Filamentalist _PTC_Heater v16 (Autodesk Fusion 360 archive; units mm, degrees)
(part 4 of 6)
sketch "Sketch176" plane through (0, 74.3239, 0) normal (0, -1, 0) x axis (1, 0, 0)
  line L1 (102.2613, 77.8502) -> (-16.9087, 77.8502)
  line L2 (103.5313, 74.9038) -> (103.5313, 76.5802)
  line L3 (109.0177, 71.0938) -> (107.3413, 71.0938)
  line L4 (110.2877, -10.1662) -> (110.2877, 69.8238)
  line L5 (107.3413, -11.4362) -> (109.0177, -11.4362)
  line L6 (109.0177, -19.0562) -> (107.3413, -19.0562)
  line L7 (110.2877, -71.6662) -> (110.2877, -20.3262)
  line L8 (107.3413, -72.9362) -> (109.0177, -72.9362)
  line L9 (109.0177, -80.5562) -> (107.3413, -80.5562)
  line L10 (110.2877, -133.1662) -> (110.2877, -81.8262)
  line L11 (107.3413, -134.4362) -> (109.0177, -134.4362)
  line L12 (109.0177, -142.0562) -> (107.3413, -142.0562)
  line L13 (110.2877, -222.8162) -> (110.2877, -143.3262)
  line L14 (107.3413, -224.0862) -> (109.0177, -224.0862)
  line L15 (103.5313, -229.5726) -> (103.5313, -227.8962)
  line L16 (-16.9087, -230.8426) -> (102.2613, -230.8426)
  line L17 (-18.1787, -227.8962) -> (-18.1787, -229.5726)
  line L18 (-23.6651, -224.0862) -> (-21.9887, -224.0862)
  line L19 (-24.9351, -143.3262) -> (-24.9351, -222.8162)
  line L20 (-21.9887, -142.0562) -> (-23.6651, -142.0562)
  line L21 (-23.6651, -134.4362) -> (-21.9887, -134.4362)
  line L22 (-24.9351, -81.8262) -> (-24.9351, -133.1662)
  line L23 (-21.9887, -80.5562) -> (-23.6651, -80.5562)
  line L24 (-23.6651, -72.9362) -> (-21.9887, -72.9362)
  line L25 (-24.9351, -20.3262) -> (-24.9351, -71.6662)
  line L26 (-21.9887, -19.0562) -> (-23.6651, -19.0562)
  line L27 (-23.6651, -11.4362) -> (-21.9887, -11.4362)
  line L28 (-24.9351, 22.1988) -> (-24.9351, -10.1662)
  line L29 (-23.2587, 22.1988) -> (-24.9351, 22.1988)
  line L30 (-23.2587, 55.8538) -> (-23.2587, 22.1988)
  line L31 (-24.9351, 55.8538) -> (-23.2587, 55.8538)
  line L32 (-24.9351, 69.8238) -> (-24.9351, 55.8538)
  line L33 (-21.9887, 71.0938) -> (-23.6651, 71.0938)
  line L34 (-18.1787, 76.5802) -> (-18.1787, 74.9038)
  line L35 (-20.8387, 78.9678) -> (106.1913, 78.9678)
  line L36 (-26.0527, -226.7462) -> (-26.0527, 73.7538)
  line L37 (106.1913, -231.9602) -> (-20.8387, -231.9602)
  line L38 (111.4053, 73.7538) -> (111.4053, -226.7462)
  circle C1 centre (-21.9887, -15.2462) radius 1.27
  circle C2 centre (107.3413, -15.2462) radius 1.27
  circle C3 centre (107.3413, -76.7462) radius 1.27
  circle C4 centre (-21.9887, -76.7462) radius 1.27
  arc A1 centre (102.2613, 76.5802) radius 1.27 clockwise from (102.2613, 77.8502) to (103.5313, 76.5802)
  arc A2 centre (107.3413, 74.9038) radius 3.81 clockwise from (107.3413, 71.0938) to (103.5313, 74.9038)
  arc A3 centre (109.0177, 69.8238) radius 1.27 clockwise from (109.0177, 71.0938) to (110.2877, 69.8238)
  arc A4 centre (109.0177, -10.1662) radius 1.27 clockwise from (110.2877, -10.1662) to (109.0177, -11.4362)
  arc A5 centre (107.3413, -15.2462) radius 3.81 clockwise from (107.3413, -19.0562) to (107.3413, -11.4362)
  arc A6 centre (109.0177, -20.3262) radius 1.27 clockwise from (109.0177, -19.0562) to (110.2877, -20.3262)
  arc A7 centre (109.0177, -71.6662) radius 1.27 clockwise from (110.2877, -71.6662) to (109.0177, -72.9362)
  arc A8 centre (107.3413, -76.7462) radius 3.81 clockwise from (107.3413, -80.5562) to (107.3413, -72.9362)
  arc A9 centre (109.0177, -81.8262) radius 1.27 clockwise from (109.0177, -80.5562) to (110.2877, -81.8262)
  arc A10 centre (109.0177, -133.1662) radius 1.27 clockwise from (110.2877, -133.1662) to (109.0177, -134.4362)
  arc A11 centre (107.3413, -138.2462) radius 3.81 clockwise from (107.3413, -142.0562) to (107.3413, -134.4362)
  arc A12 centre (109.0177, -143.3262) radius 1.27 clockwise from (109.0177, -142.0562) to (110.2877, -143.3262)
  arc A13 centre (109.0177, -222.8162) radius 1.27 clockwise from (110.2877, -222.8162) to (109.0177, -224.0862)
  arc A14 centre (107.3413, -227.8962) radius 3.81 clockwise from (103.5313, -227.8962) to (107.3413, -224.0862)
  arc A15 centre (102.2613, -229.5726) radius 1.27 clockwise from (103.5313, -229.5726) to (102.2613, -230.8426)
  arc A16 centre (-16.9087, -229.5726) radius 1.27 clockwise from (-16.9087, -230.8426) to (-18.1787, -229.5726)
  arc A17 centre (-21.9887, -227.8962) radius 3.81 clockwise from (-21.9887, -224.0862) to (-18.1787, -227.8962)
  arc A18 centre (-23.6651, -222.8162) radius 1.27 clockwise from (-23.6651, -224.0862) to (-24.9351, -222.8162)
  arc A19 centre (-23.6651, -143.3262) radius 1.27 clockwise from (-24.9351, -143.3262) to (-23.6651, -142.0562)
  arc A20 centre (-21.9887, -138.2462) radius 3.81 clockwise from (-21.9887, -134.4362) to (-21.9887, -142.0562)
  arc A21 centre (-23.6651, -133.1662) radius 1.27 clockwise from (-23.6651, -134.4362) to (-24.9351, -133.1662)
  arc A22 centre (-23.6651, -81.8262) radius 1.27 clockwise from (-24.9351, -81.8262) to (-23.6651, -80.5562)
  arc A23 centre (-21.9887, -76.7462) radius 3.81 clockwise from (-21.9887, -72.9362) to (-21.9887, -80.5562)
  arc A24 centre (-23.6651, -71.6662) radius 1.27 clockwise from (-23.6651, -72.9362) to (-24.9351, -71.6662)
  arc A25 centre (-23.6651, -20.3262) radius 1.27 clockwise from (-24.9351, -20.3262) to (-23.6651, -19.0562)
  arc A26 centre (-21.9887, -15.2462) radius 3.81 clockwise from (-21.9887, -11.4362) to (-21.9887, -19.0562)
  arc A27 centre (-23.6651, -10.1662) radius 1.27 clockwise from (-23.6651, -11.4362) to (-24.9351, -10.1662)
  arc A28 centre (-23.6651, 69.8238) radius 1.27 clockwise from (-24.9351, 69.8238) to (-23.6651, 71.0938)
  arc A29 centre (-21.9887, 74.9038) radius 3.81 clockwise from (-18.1787, 74.9038) to (-21.9887, 71.0938)
  arc A30 centre (-16.9087, 76.5802) radius 1.27 clockwise from (-18.1787, 76.5802) to (-16.9087, 77.8502)
  circle C5 centre (-21.9887, -227.8962) radius 1.27
  circle C6 centre (-21.9887, -138.2462) radius 1.27
  circle C7 centre (-21.9887, 74.9038) radius 1.27
  arc A31 centre (-20.8387, 73.7538) radius 5.214 clockwise from (-26.0527, 73.7538) to (-20.8387, 78.9678)
  arc A32 centre (-20.8387, -226.7462) radius 5.214 clockwise from (-20.8387, -231.9602) to (-26.0527, -226.7462)
  arc A33 centre (106.1913, -226.7462) radius 5.214 clockwise from (111.4053, -226.7462) to (106.1913, -231.9602)
  arc A34 centre (106.1913, 73.7538) radius 5.214 clockwise from (106.1913, 78.9678) to (111.4053, 73.7538)
  circle C8 centre (107.3413, -227.8962) radius 1.27
  circle C9 centre (107.3413, -138.2462) radius 1.27
  arc A35 centre (107.5413, 74.9038) radius 1.27 clockwise from (107.4413, 73.6377) to (107.4413, 76.1698)
  arc A36 centre (107.3413, 74.9038) radius 1.27 clockwise from (107.4413, 76.1698) to (107.4413, 73.6377)
  circle C10 centre (-21.9887, -15.2462) radius 1.65
  circle C11 centre (107.3413, -15.2462) radius 1.65
  circle C12 centre (107.3413, -76.7462) radius 1.65
  circle C13 centre (-21.9887, -76.7462) radius 1.65
  concentric C1 C10
  concentric C2 C11
  concentric C3 C12
  concentric C4 C13
  dimension "d546" diameter C10 = 3.3
  dimension "d547" diameter C11 = 3.3
  dimension "d548" diameter C12 = 3.3
  dimension "d549" diameter C13 = 3.3
extrude "Extrude4" cut sketch "Sketch176" profile of C1 C2 C3 C4 C10 C11 C12 C13 along normal blind 10
position "Position11"
sketch "Sketch177" plane through (0, 127.0628, 0) normal (0, -1, 0) x axis (1, 0, 0)
  line L1 (98.0895, -130.892) -> (98.0895, -133.242)
  line L2 (101.5895, -133.242) -> (101.5895, -130.892)
  line L3 (105.3395, -133.242) -> (101.5895, -133.242)
  line L4 (106.8395, -5.742) -> (106.8395, -131.742)
  line L5 (12.0907, -4.242) -> (105.3395, -4.242)
  line L6 (12.0907, -129.9908) -> (12.0907, -4.242)
  line L7 (91.8395, -129.9908) -> (12.0907, -129.9908)
  line L8 (93.4651, -133.242) -> (93.4651, -129.9908)
  line L9 (98.0895, -133.242) -> (93.4651, -133.242)
  arc A1 centre (99.8395, -130.892) radius 1.75 clockwise from (98.0895, -130.892) to (101.5895, -130.892)
  arc A2 centre (105.3395, -131.742) radius 1.5 clockwise from (106.8395, -131.742) to (105.3395, -133.242)
  arc A3 centre (105.3395, -5.742) radius 1.5 clockwise from (105.3395, -4.242) to (106.8395, -5.742)
  arc A4 centre (92.6523, -129.9908) radius 0.8128 clockwise from (91.8395, -129.9908) to (93.4651, -129.9908)
  circle C1 centre (14.3395, -8.742) radius 1.75
  circle C2 centre (76.3395, -82.242) radius 1.5
  circle C3 centre (43.3395, -82.242) radius 1.5
  circle C4 centre (76.3395, -40.742) radius 1.5
  circle C5 centre (99.8395, -130.892) radius 1.75
extrude "Extrude41" cut sketch "Sketch177" profile of A1 C1 C5 against normal blind 40
sketch "Sketch178" plane through (29.749, 29.749, 0) normal (0.7071, 0.7071, 0) x axis (-0.7071, 0.7071, 0)
  line L1 (77.335, -133.1662) -> (77.335, -90.6189)
  line L2 (73.1682, -134.4362) -> (75.539, -134.4362)
  line L3 (72.4498, -137.0823) -> (72.4498, -134.4702)
  line L4 (72.4498, -142.0222) -> (72.4498, -139.4102)
  line L5 (75.539, -142.0562) -> (73.1682, -142.0562)
  line L6 (78.5563, -93.8963) -> (78.5563, -139.9461)
  line L7 (69.5, -134.938) -> (78.5563, -134.938)
  line L8 (69.5, -142.5) -> (69.5, -134.938)
  line L9 (77.335, -142.5) -> (69.5, -142.5)
  line L10 (78.5563, -134.938) -> (77.335, -142.5)
  line L11 (78.5563, -134.4702) -> (72.4498, -134.4702)
  line L12 (78.5563, -134.4702) -> (78.5563, -134.938)
  line L13 (78.5563, -134.4702) -> (78.5563, -139.6386)
  line L14 (69.5, -138.719) -> (78.5563, -139.0476)
  closed curve K1 centre (75.539, -133.1662)
  closed curve K2 centre (73.1682, -138.2462)
  closed curve K3 centre (73.1682, -138.2462)
  closed curve K4 centre (73.1682, -138.2462)
  closed curve K5 centre (75.539, -143.3262)
  closed curve K6 centre (98.1333, -145.3462)
  closed curve K7 centre (98.1333, -88.4962)
  point P20 (78.5563, -134.938)
  point P7 (72.4498, -134.4702)
  point P24 (72.4498, -134.4702)
  point P25 (78.5563, -134.4702)
  point P26 (78.5563, -139.6386)
  point P27 (78.5563, -139.0476)
  point P28 (69.5, -138.719)
  coincident L6 P20
  perpendicular L3 L7
  perpendicular L7 L8
  perpendicular L6 L9
  coincident P7 P24
  coincident L6 P25
  perpendicular L6 L11
  coincident L6 P26
  coincident L13 P27
  midpoint L8 P28
extrude "Extrude57" new body sketch "Sketch178" profile of L3 K3 L7 L10 L14 along normal blind 4.5
sketch "Sketch179" plane through (0, 0, -134.938) normal (0, 0, 1) x axis (-1, 0, 0)
  line L1 (21.4807, -80.9787) -> (25.7987, -85.2967)
  line L2 (18.2987, -84.1607) -> (21.4807, -80.9787)
  line L3 (22.6167, -88.4787) -> (18.2987, -84.1607)
  line L4 (25.7987, -85.2967) -> (22.6167, -88.4787)
  line L5 (-85, -85) -> (21.4807, -80.9787)
  line L6 (15.3483, -81.2103) -> (22.6167, -88.4787)
  point P3 (21.4807, -80.9787)
  point P6 (21.4807, -80.9787)
  point P5 (22.6167, -88.4787)
  point P8 (22.6167, -88.4787)
  point P9 (15.3483, -81.2103)
  coincident P3 P6
  coincident P5 P8
  coincident L5 P9
  perpendicular L4 L6
extrude "Extrude58" new body sketch "Sketch179" along normal blind 1
move "Move26"
sketch "Sketch180" plane through (0, 0, -64.938) normal (0, 0, -1) x axis (1, 0, 0)
  line L1 (-25.7987, -85.2967) -> (-21.4807, -80.9787)
  line L2 (-22.6167, -88.4787) -> (-25.7987, -85.2967)
  line L3 (-15.3483, -81.2103) -> (-22.6167, -88.4787)
  line L4 (-21.4807, -80.9787) -> (-15.3483, -81.2103)
extrude "Extrude42" cut sketch "Sketch180" along normal blind 20
delete_face "DeleteFace23"
remove_body "RemoveBody3"
sketch "Sketch181" plane through (0, 0, -63.938) normal (0, 0, 1) x axis (-1, 0, 0)
  line L1 (21.4807, -80.9787) -> (25.7987, -85.2967)
  line L2 (15.3483, -81.2103) -> (21.4807, -80.9787)
  line L3 (22.6167, -88.4787) -> (15.3483, -81.2103)
  line L4 (25.7987, -85.2967) -> (22.6167, -88.4787)
extrude "Extrude43" cut sketch "Sketch181" along normal blind 60
remove_body "RemoveBody4"
mirror "Mirror2" mirrorStitchTolerance 0.1
move "Move27"
move "Move28"
move "Move29"
move "Move30"
move "Move31"
sketch "Sketch182" plane through (0, 0, -64.938) normal (0, 0, 1) x axis (-1, 0, 0)
  line L1 (-111.1516, -85.6903) -> (-107.0006, -81.2116)
  line L2 (-107.8512, -88.7493) -> (-111.1516, -85.6903)
  line L3 (-100.8638, -81.2103) -> (-107.8512, -88.7493)
  line L4 (-107.0006, -81.2116) -> (-100.8638, -81.2103)
extrude "Extrude44" cut sketch "Sketch182" along normal blind 60
sketch "Sketch183" plane through (0, 0, -65.938) normal (0, 0, -1) x axis (1, 0, 0)
  line L1 (107.0006, -81.2116) -> (111.1516, -85.6903)
  line L2 (100.8638, -81.2103) -> (107.0006, -81.2116)
  line L3 (107.8512, -88.7493) -> (100.8638, -81.2103)
  line L4 (111.1516, -85.6903) -> (107.8512, -88.7493)
extrude "Extrude45" cut sketch "Sketch183" along normal blind 19
remove_body "RemoveBody187"
remove_body "RemoveBody188"
remove_body "RemoveBody189"
remove_body "RemoveBody190"
remove_body "RemoveBody5"
remove_body "RemoveBody6"
position "Position12"
sketch "Sketch184" plane through (0, 72.0887, 0) normal (0, -1, 0) x axis (1, 0, 0)
  line L1 (106.1913, 78.9678) -> (-20.8387, 78.9678)
  line L2 (111.4053, -226.7462) -> (111.4053, 73.7538)
  line L3 (-20.8387, -231.9602) -> (106.1913, -231.9602)
  line L4 (-26.0527, 73.7538) -> (-26.0527, -226.7462)
  line L5 (-20.8387, 81.2538) -> (106.3913, 81.2538)
  line L6 (-28.3387, -226.7462) -> (-28.3387, 73.7538)
  line L7 (106.3913, -234.2462) -> (-20.8387, -234.2462)
  line L8 (113.8913, 73.7538) -> (113.8913, -226.7462)
  line L9 (130, -30) -> (-50, -30)
  line L10 (130, -40) -> (130, -30)
  line L11 (-50, -40) -> (130, -40)
  line L12 (-50, -30) -> (-50, -40)
  arc A1 centre (106.1913, 73.7538) radius 5.214 clockwise from (106.1913, 78.9678) to (111.4053, 73.7538)
  arc A2 centre (106.1913, -226.7462) radius 5.214 clockwise from (111.4053, -226.7462) to (106.1913, -231.9602)
  arc A3 centre (-20.8387, -226.7462) radius 5.214 clockwise from (-20.8387, -231.9602) to (-26.0527, -226.7462)
  arc A4 centre (-20.8387, 73.7538) radius 5.214 clockwise from (-26.0527, 73.7538) to (-20.8387, 78.9678)
  arc A5 centre (-20.8387, 73.7538) radius 7.5 clockwise from (-28.3387, 73.7538) to (-20.8387, 81.2538)
  arc A6 centre (-20.8387, -226.7462) radius 7.5 clockwise from (-20.8387, -234.2462) to (-28.3387, -226.7462)
  arc A7 centre (106.3913, -226.7462) radius 7.5 clockwise from (113.8913, -226.7462) to (106.3913, -234.2462)
  arc A8 centre (106.3913, 73.7538) radius 7.5 clockwise from (106.3913, 81.2538) to (113.8913, 73.7538)
  horizontal L9
  vertical L10
  horizontal L11
  vertical L12
extrude "Extrude46" cut sketch "Sketch184" profile of L2 L4 L6 L8 L9 L10 L11 L12 distance 270
move "Move5"
move "Move6"
combine "Combine6"
combine "Combine3"
position "Position13"
sketch "Sketch185" plane through (0, 74.3239, 0) normal (0, -1, 0) x axis (1, 0, 0)
  line L1 (111.4053, 73.7538) -> (111.4053, -216.7462)
  line L2 (-20.8387, 78.9678) -> (106.1913, 78.9678)
  line L3 (-26.0527, -216.7462) -> (-26.0527, 73.7538)
  line L4 (106.1913, -221.9602) -> (-20.8387, -221.9602)
  line L5 (110.2877, -61.6662) -> (110.2877, -20.3262)
  line L6 (107.3413, -62.9362) -> (109.0177, -62.9362)
  line L7 (109.0177, -70.5562) -> (107.3413, -70.5562)
  line L8 (110.2877, -123.1662) -> (110.2877, -71.8262)
  line L9 (107.3413, -124.4362) -> (109.0177, -124.4362)
  line L10 (109.0177, -132.0562) -> (107.3413, -132.0562)
  line L11 (110.2877, -212.8162) -> (110.2877, -133.3262)
  line L12 (107.3413, -214.0862) -> (109.0177, -214.0862)
  line L13 (103.5313, -219.5726) -> (103.5313, -217.8962)
  line L14 (-16.9087, -220.8426) -> (102.2613, -220.8426)
  line L15 (-18.1787, -217.8962) -> (-18.1787, -219.5726)
  line L16 (-23.6651, -214.0862) -> (-21.9887, -214.0862)
  line L17 (-24.9351, -133.3262) -> (-24.9351, -212.8162)
  line L18 (-21.9887, -132.0562) -> (-23.6651, -132.0562)
  line L19 (-23.6651, -124.4362) -> (-21.9887, -124.4362)
  line L20 (-24.9351, -71.8262) -> (-24.9351, -123.1662)
  line L21 (-21.9887, -70.5562) -> (-23.6651, -70.5562)
  line L22 (-23.6651, -62.9362) -> (-21.9887, -62.9362)
  line L23 (-24.9351, -20.3262) -> (-24.9351, -61.6662)
  line L24 (-21.9887, -19.0562) -> (-23.6651, -19.0562)
  line L25 (-23.6651, -11.4362) -> (-21.9887, -11.4362)
  line L26 (-24.9351, 22.1988) -> (-24.9351, -10.1662)
  line L27 (-23.2587, 22.1988) -> (-24.9351, 22.1988)
  line L28 (-23.2587, 55.8538) -> (-23.2587, 22.1988)
  line L29 (-24.9351, 55.8538) -> (-23.2587, 55.8538)
  line L30 (-24.9351, 69.8238) -> (-24.9351, 55.8538)
  line L31 (-21.9887, 71.0938) -> (-23.6651, 71.0938)
  line L32 (-18.1787, 76.5802) -> (-18.1787, 74.9038)
  line L33 (102.2613, 77.8502) -> (-16.9087, 77.8502)
  line L34 (103.5313, 74.9038) -> (103.5313, 76.5802)
  line L35 (109.0177, 71.0938) -> (107.3413, 71.0938)
  line L36 (110.2877, -10.1662) -> (110.2877, 69.8238)
  line L37 (107.3413, -11.4362) -> (109.0177, -11.4362)
  line L38 (109.0177, -19.0562) -> (107.3413, -19.0562)
  line L39 (-16, -55.8158) -> (-24.9351, -55.8158)
  line L40 (-16, -77) -> (-16, -55.8158)
  line L41 (-24.9351, -77) -> (-16, -77)
  line L42 (-24.9351, -55.8158) -> (-24.9351, -77)
  line L43 (103, -56.3876) -> (110.2877, -56.3876)
  line L44 (103, -77) -> (103, -56.3876)
  line L45 (110.2877, -77) -> (103, -77)
  line L46 (110.2877, -56.3876) -> (110.2877, -77)
  arc A1 centre (106.1913, 73.7538) radius 5.214 clockwise from (106.1913, 78.9678) to (111.4053, 73.7538)
  arc A2 centre (-20.8387, 73.7538) radius 5.214 clockwise from (-26.0527, 73.7538) to (-20.8387, 78.9678)
  arc A3 centre (-20.8387, -216.7462) radius 5.214 clockwise from (-20.8387, -221.9602) to (-26.0527, -216.7462)
  arc A4 centre (106.1913, -216.7462) radius 5.214 clockwise from (111.4053, -216.7462) to (106.1913, -221.9602)
  circle C1 centre (107.3413, -66.7462) radius 1.27
  circle C2 centre (-21.9887, -66.7462) radius 1.27
  circle C3 centre (-21.9887, -217.8962) radius 1.27
  circle C4 centre (-21.9887, -128.2462) radius 1.27
  circle C5 centre (107.3413, -217.8962) radius 1.27
  circle C6 centre (107.3413, -128.2462) radius 1.27
  arc A5 centre (109.0177, -61.6662) radius 1.27 clockwise from (110.2877, -61.6662) to (109.0177, -62.9362)
  arc A6 centre (107.3413, -66.7462) radius 3.81 clockwise from (107.3413, -70.5562) to (107.3413, -62.9362)
  arc A7 centre (109.0177, -71.8262) radius 1.27 clockwise from (109.0177, -70.5562) to (110.2877, -71.8262)
  arc A8 centre (109.0177, -123.1662) radius 1.27 clockwise from (110.2877, -123.1662) to (109.0177, -124.4362)
  arc A9 centre (107.3413, -128.2462) radius 3.81 clockwise from (107.3413, -132.0562) to (107.3413, -124.4362)
  arc A10 centre (109.0177, -133.3262) radius 1.27 clockwise from (109.0177, -132.0562) to (110.2877, -133.3262)
  arc A11 centre (109.0177, -212.8162) radius 1.27 clockwise from (110.2877, -212.8162) to (109.0177, -214.0862)
  arc A12 centre (107.3413, -217.8962) radius 3.81 clockwise from (103.5313, -217.8962) to (107.3413, -214.0862)
  arc A13 centre (102.2613, -219.5726) radius 1.27 clockwise from (103.5313, -219.5726) to (102.2613, -220.8426)
  arc A14 centre (-16.9087, -219.5726) radius 1.27 clockwise from (-16.9087, -220.8426) to (-18.1787, -219.5726)
  arc A15 centre (-21.9887, -217.8962) radius 3.81 clockwise from (-21.9887, -214.0862) to (-18.1787, -217.8962)
  arc A16 centre (-23.6651, -212.8162) radius 1.27 clockwise from (-23.6651, -214.0862) to (-24.9351, -212.8162)
  arc A17 centre (-23.6651, -133.3262) radius 1.27 clockwise from (-24.9351, -133.3262) to (-23.6651, -132.0562)
  arc A18 centre (-21.9887, -128.2462) radius 3.81 clockwise from (-21.9887, -124.4362) to (-21.9887, -132.0562)
  arc A19 centre (-23.6651, -123.1662) radius 1.27 clockwise from (-23.6651, -124.4362) to (-24.9351, -123.1662)
  arc A20 centre (-23.6651, -71.8262) radius 1.27 clockwise from (-24.9351, -71.8262) to (-23.6651, -70.5562)
  arc A21 centre (-21.9887, -66.7462) radius 3.81 clockwise from (-21.9887, -62.9362) to (-21.9887, -70.5562)
  arc A22 centre (-23.6651, -61.6662) radius 1.27 clockwise from (-23.6651, -62.9362) to (-24.9351, -61.6662)
  arc A23 centre (-23.6651, -20.3262) radius 1.27 clockwise from (-24.9351, -20.3262) to (-23.6651, -19.0562)
  arc A24 centre (-21.9887, -15.2462) radius 3.81 clockwise from (-21.9887, -11.4362) to (-21.9887, -19.0562)
  arc A25 centre (-23.6651, -10.1662) radius 1.27 clockwise from (-23.6651, -11.4362) to (-24.9351, -10.1662)
  arc A26 centre (-23.6651, 69.8238) radius 1.27 clockwise from (-24.9351, 69.8238) to (-23.6651, 71.0938)
  arc A27 centre (-21.9887, 74.9038) radius 3.81 clockwise from (-18.1787, 74.9038) to (-21.9887, 71.0938)
  arc A28 centre (-16.9087, 76.5802) radius 1.27 clockwise from (-18.1787, 76.5802) to (-16.9087, 77.8502)
  arc A29 centre (102.2613, 76.5802) radius 1.27 clockwise from (102.2613, 77.8502) to (103.5313, 76.5802)
  arc A30 centre (107.3413, 74.9038) radius 3.81 clockwise from (107.3413, 71.0938) to (103.5313, 74.9038)
  arc A31 centre (109.0177, 69.8238) radius 1.27 clockwise from (109.0177, 71.0938) to (110.2877, 69.8238)
  arc A32 centre (109.0177, -10.1662) radius 1.27 clockwise from (110.2877, -10.1662) to (109.0177, -11.4362)
  arc A33 centre (107.3413, -15.2462) radius 3.81 clockwise from (107.3413, -19.0562) to (107.3413, -11.4362)
  arc A34 centre (109.0177, -20.3262) radius 1.27 clockwise from (109.0177, -19.0562) to (110.2877, -20.3262)
  circle C7 centre (-21.9887, -15.2462) radius 1.27
  circle C8 centre (107.3413, -15.2462) radius 1.27
  circle C9 centre (-21.9887, 74.9038) radius 1.27
  arc A35 centre (107.5413, 74.9038) radius 1.27 clockwise from (107.4413, 73.6377) to (107.4413, 76.1698)
  arc A36 centre (107.3413, 74.9038) radius 1.27 clockwise from (107.4413, 76.1698) to (107.4413, 73.6377)
  point P111 (-24.9351, -55.8158)
  point P115 (110.2877, -56.3876)
  horizontal L39
  vertical L40
  horizontal L41
  vertical L42
  coincident L23 P111
  horizontal L43
  vertical L44
  horizontal L45
  vertical L46
  coincident L5 P115
extrude "Extrude47" cut sketch "Sketch185" profile of C1 C2 L5 A5 L6 A6 L7 A7 L8 L20 A20 L21 A21 L22 A22 L23 L39 L40 L41 L42 L43 L44 L45 L46 against normal blind 8
delete_face "DeleteFace24"
sketch "Sketch186" plane through (0, 82.3239, 0) normal (0, -1, 0) x axis (1, 0, 0)
  line L1 (-22.8259, -62.9362) -> (-22.8259, -70.5562)
  line L2 (-23.6651, -62.9362) -> (-22.8259, -62.9362)
  line L3 (-24.9351, -71.8262) -> (-24.9351, -61.6662)
  line L4 (-22.8259, -70.5562) -> (-23.6651, -70.5562)
  arc A1 centre (-23.6651, -61.6662) radius 1.27 clockwise from (-23.6651, -62.9362) to (-24.9351, -61.6662)
  arc A2 centre (-23.6651, -71.8262) radius 1.27 clockwise from (-24.9351, -71.8262) to (-23.6651, -70.5562)
extrude "Extrude48" cut sketch "Sketch186" against normal blind 3
sketch "Sketch187" plane through (0, 82.3239, 0) normal (0, -1, 0) x axis (1, 0, 0)
  line L1 (108.0315, -62.9362) -> (109.0177, -62.9362)
  line L2 (108.0315, -65.6802) -> (108.0315, -62.9362)
  line L3 (108.0315, -70.5562) -> (108.0315, -67.8123)
  line L4 (109.0177, -70.5562) -> (108.0315, -70.5562)
  line L5 (110.2877, -61.6662) -> (110.2877, -71.8262)
  arc A1 centre (109.0177, -61.6662) radius 1.27 clockwise from (110.2877, -61.6662) to (109.0177, -62.9362)
  arc A2 centre (107.3413, -66.7462) radius 1.27 clockwise from (108.0315, -65.6802) to (108.0315, -67.8123)
  arc A3 centre (109.0177, -71.8262) radius 1.27 clockwise from (109.0177, -70.5562) to (110.2877, -71.8262)
extrude "Extrude49" cut sketch "Sketch187" against normal blind 4
sketch "Sketch188" plane through (111.1513, 0, 0) normal (-1, 0, 0) x axis (0, -1, 0)
  line L1 (-85.2967, 73.7538) -> (-85.2967, -216.7462)
  line L2 (-129.2387, 73.7538) -> (-85.2967, 73.7538)
  line L3 (-129.2387, -216.7462) -> (-129.2387, 73.7538)
  line L4 (-85.2967, -216.7462) -> (-129.2387, -216.7462)
  line L5 (-85.6906, -55.938) -> (-85.6906, -74.938)
  line L6 (-85.69, -55.938) -> (-85.6906, -55.938)
  line L7 (-85.69, -74.938) -> (-85.69, -55.938)
  line L8 (-85.6906, -74.938) -> (-85.69, -74.938)
  line L9 (-85.69, -54.938) -> (-85.69, -4.938)
  line L10 (-85.6906, -54.938) -> (-85.69, -54.938)
  line L11 (-85.6906, -4.938) -> (-85.6906, -54.938)
  line L12 (-85.69, -4.938) -> (-85.6906, -4.938)
  line L13 (-86.2407, -4.3074) -> (-85.2967, -4.3074)
  line L14 (-86.2407, -75.3836) -> (-86.2407, -4.3074)
  line L15 (-85.2967, -75.3836) -> (-86.2407, -75.3836)
  line L16 (-85.2967, -4.3074) -> (-85.2967, -75.3836)
  point P14 (-85.2967, -4.3074)
  horizontal L13
  vertical L14
  horizontal L15
  vertical L16
  coincident L1 P14
extrude "Extrude50" cut sketch "Sketch188" profile of L1 L5 L6 L7 L8 L9 L10 L11 L12 L13 L14 L15 L16 against normal blind 10 bodies "Body (1)"
remove_body "RemoveBody7"
remove_body "RemoveBody8"
delete_face "DeleteFace25"
sketch "Sketch189" plane through (0, 127.0628, 0) normal (0, -1, 0) x axis (1, 0, 0)
  line L1 (98.0895, -120.892) -> (98.0895, -123.242)
  line L2 (101.5895, -123.242) -> (101.5895, -120.892)
  line L3 (105.3395, -123.242) -> (101.5895, -123.242)
  line L4 (106.8395, 4.258) -> (106.8395, -121.742)
  line L5 (12.0907, 5.758) -> (105.3395, 5.758)
  line L6 (12.0907, -119.9908) -> (12.0907, 5.758)
  line L7 (91.8395, -119.9908) -> (12.0907, -119.9908)
  line L8 (93.4651, -123.242) -> (93.4651, -119.9908)
  line L9 (98.0895, -123.242) -> (93.4651, -123.242)
  arc A1 centre (99.8395, -120.892) radius 1.75 clockwise from (98.0895, -120.892) to (101.5895, -120.892)
  arc A2 centre (105.3395, -121.742) radius 1.5 clockwise from (106.8395, -121.742) to (105.3395, -123.242)
  arc A3 centre (105.3395, 4.258) radius 1.5 clockwise from (105.3395, 5.758) to (106.8395, 4.258)
  arc A4 centre (92.6523, -119.9908) radius 0.8128 clockwise from (91.8395, -119.9908) to (93.4651, -119.9908)
  circle C1 centre (14.3395, 1.258) radius 1.75
  circle C2 centre (76.3395, -72.242) radius 1.5
  circle C3 centre (43.3395, -72.242) radius 1.5
  circle C4 centre (76.3395, -30.742) radius 1.5
  circle C5 centre (14.3395, 1.258) radius 1.1
  concentric C1 C5
  dimension "d580" diameter C5 = 2.2
extrude "Extrude51" cut sketch "Sketch189" profile of C5 against normal blind 25
offset_faces "OffsetFaces3" distance 0.6
delete_face "DeleteFace1"
delete_face "DeleteFace2"
offset_faces "OffsetFaces1" distance 2
sketch "Sketch190" plane through (0, -74.0232, 0) normal (0, 1, 0) x axis (-1, 0, 0)
  line L1 (-111.485, -216.849) -> (-111.485, 73.651)
  line L2 (20.8387, -221.809) -> (-106.525, -221.809)
  line L3 (25.7987, 73.651) -> (25.7987, -216.849)
  line L4 (-106.525, 78.611) -> (20.8387, 78.611)
  line L5 (20.8387, 73.651) -> (-106.525, 73.651)
  line L6 (20.8387, -216.849) -> (20.8387, 73.651)
  line L7 (-106.525, -216.849) -> (20.8387, -216.849)
  line L8 (-106.525, 73.651) -> (-106.525, -216.849)
  line L9 (-103.525, 73.651) -> (-106.525, 73.651)
  line L10 (-103.525, 70.651) -> (-103.525, 73.651)
  line L11 (-106.525, 70.651) -> (-103.525, 70.651)
  line L12 (-106.525, 73.651) -> (-106.525, 70.651)
  line L13 (17.8387, 73.651) -> (20.8387, 73.651)
  line L14 (17.8387, 70.651) -> (17.8387, 73.651)
  line L15 (20.8387, 70.651) -> (17.8387, 70.651)
  line L16 (20.8387, 73.651) -> (20.8387, 70.651)
  line L17 (-103.525, -216.849) -> (-106.525, -216.849)
  line L18 (-103.525, -213.849) -> (-103.525, -216.849)
  line L19 (-106.525, -213.849) -> (-103.525, -213.849)
  line L20 (-106.525, -216.849) -> (-106.525, -213.849)
  line L21 (17.8387, -216.849) -> (20.8387, -216.849)
  line L22 (17.8387, -213.849) -> (17.8387, -216.849)
  line L23 (20.8387, -213.849) -> (17.8387, -213.849)
  line L24 (20.8387, -216.849) -> (20.8387, -213.849)
  line L25 (17.8387, 70.651) -> (-103.525, 70.651)
  line L26 (17.8387, -213.849) -> (17.8387, 70.651)
  line L27 (-103.525, -213.849) -> (17.8387, -213.849)
  line L28 (-103.525, 70.651) -> (-103.525, -213.849)
  circle C1 centre (-107.3413, -15.2462) radius 1.65
  circle C2 centre (21.9887, -15.2462) radius 1.65
  circle C3 centre (21.9887, 74.801) radius 1.651
  circle C4 centre (-107.675, 74.801) radius 1.651
  circle C5 centre (21.9887, -128.349) radius 1.651
  circle C6 centre (21.9887, -217.999) radius 1.651
  arc A1 centre (-106.525, -216.849) radius 4.96 clockwise from (-106.525, -221.809) to (-111.485, -216.849)
  arc A2 centre (20.8387, -216.849) radius 4.96 clockwise from (25.7987, -216.849) to (20.8387, -221.809)
  arc A3 centre (20.8387, 73.651) radius 4.96 clockwise from (20.8387, 78.611) to (25.7987, 73.651)
  arc A4 centre (-106.525, 73.651) radius 4.96 clockwise from (-111.485, 73.651) to (-106.525, 78.611)
  circle C7 centre (-107.675, -128.349) radius 1.651
  circle C8 centre (-107.675, -217.999) radius 1.651
  circle C9 centre (-106.525, 73.651) radius 4.96
  circle C10 centre (20.8387, 73.651) radius 4.96
  circle C11 centre (20.8387, -216.849) radius 4.96
  circle C12 centre (-106.525, -216.849) radius 4.96
  point P8 (-111.485, 73.651)
  point P14 (20.8387, -216.849)
  point P28 (20.8387, -216.849)
  point P22 (-106.525, 73.651)
  point P26 (-106.525, 73.651)
  point P30 (-106.525, 73.651)
  point P23 (20.8387, 73.651)
  point P34 (20.8387, 73.651)
  point P25 (-106.525, -216.849)
  point P38 (-106.525, -216.849)
  point P24 (20.8387, -216.849)
  point P42 (20.8387, -216.849)
  point P31 (-103.525, 73.651)
  point P33 (-106.525, 70.651)
  point P37 (20.8387, 70.651)
  point P35 (17.8387, 73.651)
  point P39 (-103.525, -216.849)
  point P41 (-106.525, -213.849)
  point P43 (17.8387, -216.849)
  point P45 (20.8387, -213.849)
  coincident P8 C9
  horizontal L5
  vertical L6
  horizontal L7
  vertical L8
  coincident P14 P28
  coincident P22 P26
  horizontal L9
  vertical L10
  horizontal L11
  vertical L12
  coincident P22 P30
  horizontal L13
  vertical L14
  horizontal L15
  vertical L16
  coincident P23 P34
  horizontal L17
  vertical L18
  horizontal L19
  vertical L20
  coincident P25 P38
  horizontal L21
  vertical L22
  horizontal L23
  vertical L24
  coincident P24 P42
  horizontal L25
  vertical L26
  horizontal L27
  vertical L28
  dimension "d585" distance P30 P31 = 3
  dimension "d586" distance P30 P33 = 3
  dimension "d587" distance P34 P37 = 3
  dimension "d588" distance P34 P35 = 3
  dimension "d589" distance P38 P39 = 3
  dimension "d590" distance P38 P41 = 3
  dimension "d591" distance P42 P43 = 3
  dimension "d592" distance P42 P45 = 3
extrude "Extrude6" cut sketch "Sketch190" profile of C9 C10 C11 C12 L25 L26 L27 L28 against normal blind 3.981
fillet "Fillet1" radius 5
fillet "Fillet2" radius 1
fillet "Fillet3" radius 0.7
fillet "Fillet4" radius 0.4
delete_face "DeleteFace26"
delete_face "DeleteFace27"
delete_face "DeleteFace28"
delete_face "DeleteFace29"
delete_face "DeleteFace30"
delete_face "DeleteFace31"
delete_face "DeleteFace32"
delete_face "DeleteFace33"
delete_face "DeleteFace34"
delete_face "DeleteFace35"
sketch "Sketch191" plane through (0, 127.2387, 0) normal (0, -1, 0) x axis (1, 0, 0)
  line L1 (113.8913, -216.7462) -> (113.8913, 73.7538)
  line L2 (-20.8387, -224.2462) -> (106.3913, -224.2462)
  line L3 (-28.3387, 73.7538) -> (-28.3387, -216.7462)
  line L4 (106.3913, 81.2538) -> (-20.8387, 81.2538)
  line L5 (-40.8387, 102.7538) -> (126.3913, 102.7538)
  line L6 (-40.8387, 4.05) -> (-40.8387, 102.7538)
  line L7 (-40.839, 4.05) -> (-40.8387, 4.05)
  line L8 (-40.839, -109.7) -> (-40.839, 4.05)
  line L9 (-40.8387, -109.7) -> (-40.839, -109.7)
  line L10 (-40.8387, -236.7462) -> (-40.8387, -109.7)
  line L11 (126.1913, -236.7462) -> (-40.8387, -236.7462)
  line L12 (126.1913, -109.7) -> (126.1913, -236.7462)
  line L13 (126.1916, -109.7) -> (126.1913, -109.7)
  line L14 (126.1916, 4.05) -> (126.1916, -109.7)
  line L15 (126.1913, 4.05) -> (126.1916, 4.05)
  line L16 (126.1913, 41.3578) -> (126.1913, 4.05)
  line L17 (126.3913, 41.3578) -> (126.1913, 41.3578)
  line L18 (126.3913, 102.7538) -> (126.3913, 41.3578)
  line L19 (113.8913, 41.1685) -> (113.8913, -216.7462)
  line L20 (-25.3387, 81.2538) -> (-25.3387, 102.7538)
  line L21 (110.8913, 81.2538) -> (110.8913, 102.7538)
  line L22 (-25.3387, -224.2462) -> (-25.3387, -236.7462)
  line L23 (110.8913, -224.2462) -> (110.8913, -236.7462)
  line L24 (110.8913, 102.7538) -> (110.8913, -236.7462)
  line L25 (-25.3387, -236.7462) -> (-25.3387, 102.7538)
  line L26 (-28.3387, 4.462) -> (-28.3387, 73.7538)
  line L27 (113.8913, 41.1685) -> (113.8913, 73.7538)
  line L28 (-28.3387, 73.7538) -> (-28.3387, -216.7462)
  circle C1 centre (121.1913, 2.7088) radius 2.6
  arc A1 centre (106.3913, -216.7462) radius 7.5 clockwise from (113.8913, -216.7462) to (106.3913, -224.2462)
  arc A2 centre (-20.8387, -216.7462) radius 7.5 clockwise from (-20.8387, -224.2462) to (-28.3387, -216.7462)
  arc A3 centre (-20.8387, 73.7538) radius 7.5 clockwise from (-28.3387, 73.7538) to (-20.8387, 81.2538)
  arc A4 centre (106.3913, 73.7538) radius 7.5 clockwise from (106.3913, 81.2538) to (113.8913, 73.7538)
  circle C2 centre (121.1913, -190.7462) radius 2.6
  circle C3 centre (121.1913, -110.7912) radius 2.6
  circle C4 centre (-35.8387, -190.7462) radius 2.6
  circle C5 centre (-35.8387, -110.7912) radius 2.6
  point P33 (-28.3387, 4.462)
  point P34 (113.8913, 41.1685)
  point P39 (-25.3387, -236.7462)
  point P40 (110.8913, -236.7462)
  point P41 (110.8913, 102.7538)
  point P42 (-25.3387, 102.7538)
  coincident L3 P33
  coincident L1 P34
  vertical L19
  vertical L20
  vertical L21
  vertical L22
  vertical L23
  vertical L24
  vertical L25
  coincident L11 P39
  coincident L11 P40
  coincident L5 P41
  coincident L5 P42
extrude "Extrude52" cut sketch "Sketch191" profile of C1 L1 A1 A2 L3 A3 A4 C2 C3 C4 C5 L5 L6 L7 L8 L9 L10 L11 L12 L13 L14 L15 L16 L17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 against normal blind 60
sketch "Sketch192" plane through (0, 0, -236.7462) normal (0, 0, -1) x axis (1, 0, 0)
  line L1 (110.8913, -127.2387) -> (110.8913, -131.7787)
  line L2 (-25.3387, -127.2387) -> (110.8913, -127.2387)
  line L3 (-25.3387, -131.7787) -> (-25.3387, -127.2387)
  line L4 (110.8913, -131.7787) -> (-25.3387, -131.7787)
extrude "Extrude53" add sketch "Sketch192" along normal blind 9
fillet "Fillet2" radius 5
fillet "Fillet3" radius 5
fillet "Fillet4" radius 2
delete_face "DeleteFace36"
sketch "Sketch193" plane through (0, 131.7787, 0) normal (0, 1, 0) x axis (-1, 0, 0)
  line L1 (20.3387, -245.7462) -> (-105.8913, -245.7462)
  line L2 (25.3387, -224.8703) -> (25.3387, -240.7462)
  line L3 (28.3387, 73.7538) -> (28.3387, -216.7462)
  line L4 (25.3387, 97.7538) -> (25.3387, 81.8778)
  line L5 (-105.8913, 102.7538) -> (20.3387, 102.7538)
  line L6 (-110.8913, 81.8778) -> (-110.8913, 97.7538)
  line L7 (-113.8913, -216.7462) -> (-113.8913, 73.7538)
  line L8 (-110.8913, -240.7462) -> (-110.8913, -224.8703)
  line L9 (-76.1597, 56.4579) -> (-80.4032, 60.7014)
  line L10 (-80.4031, 22.0143) -> (-76.1597, 26.2578)
  line L11 (-88, 44.8573) -> (-88, 37.8584)
  line L12 (-54.4515, 36.1073) -> (-50.2044, 31.8602)
  line L13 (-50.2044, 50.8555) -> (-54.4515, 46.6084)
  line L14 (-70.5577, 30.5022) -> (-74.8019, 26.258)
  line L15 (-45.9598, 26.258) -> (-50.204, 30.5022)
  line L16 (-49.5252, 31.181) -> (-45.281, 26.9368)
  line L17 (-45.2809, 55.779) -> (-49.5252, 51.5347)
  line L18 (-55.8105, 36.1087) -> (-60.3808, 40.6791)
  line L19 (-60.3808, 40.6791) -> (-64.9512, 36.1087)
  line L20 (-74.802, 56.4578) -> (-70.5577, 52.2135)
  line L21 (-50.204, 52.2135) -> (-45.9597, 56.4578)
  line L22 (-45.2808, 57.1367) -> (-41.0373, 61.3802)
  line L23 (-79.7244, 61.3802) -> (-75.4809, 57.1367)
  line L24 (-64.9512, 46.607) -> (-60.3808, 42.0366)
  line L25 (-60.3808, 42.0366) -> (-55.8105, 46.607)
  line L26 (-69.8785, 51.5343) -> (-65.6314, 47.2872)
  line L27 (-55.1303, 47.2872) -> (-50.8832, 51.5343)
  line L28 (-65.63, 36.7875) -> (-61.0596, 41.3578)
  line L29 (-61.0596, 41.3578) -> (-65.63, 45.9282)
  line L30 (-70.5573, 31.8602) -> (-66.3102, 36.1073)
  line L31 (-66.3102, 46.6084) -> (-70.5573, 50.8555)
  line L32 (-55.1317, 45.9282) -> (-59.7021, 41.3578)
  line L33 (-59.7021, 41.3578) -> (-55.1317, 36.7875)
  line L34 (-65.6314, 35.4285) -> (-69.8785, 31.1814)
  line L35 (-50.8832, 31.1814) -> (-55.1303, 35.4285)
  line L36 (-41.0373, 21.3355) -> (-45.2808, 25.579)
  line L37 (-75.4809, 25.579) -> (-79.7243, 21.3355)
  line L38 (-40.3585, 60.7014) -> (-44.602, 56.4579)
  line L39 (-44.602, 26.2578) -> (-40.3585, 22.0143)
  line L40 (-75.4807, 26.9368) -> (-71.2365, 31.181)
  line L41 (-71.2365, 51.5347) -> (-75.4808, 55.779)
  line L42 (-23.6119, 72.6775) -> (-94.6955, 72.6775)
  line L43 (-23.6119, 8.9929) -> (-23.6119, 72.6775)
  line L44 (-94.6955, 8.9929) -> (-23.6119, 8.9929)
  line L45 (-94.6955, 72.6775) -> (-94.6955, 8.9929)
  line L46 (-27, 74) -> (-96, 74)
  line L47 (-27, 7) -> (-27, 74)
  line L48 (-96, 7) -> (-27, 7)
  line L49 (-96, 74) -> (-96, 7)
  arc A1 centre (-105.8913, -240.7462) radius 5 clockwise from (-105.8913, -245.7462) to (-110.8913, -240.7462)
  arc A2 centre (20.3387, -240.7462) radius 5 clockwise from (25.3387, -240.7462) to (20.3387, -245.7462)
  arc A3 centre (30.3387, -224.8703) radius 5 clockwise from (25.3387, -224.8703) to (26.5387, -221.6206)
  arc A4 centre (20.8387, -216.7462) radius 7.5 clockwise from (28.3387, -216.7462) to (26.5387, -221.6206)
  arc A5 centre (20.8387, 73.7538) radius 7.5 clockwise from (26.5387, 78.6282) to (28.3387, 73.7538)
  arc A6 centre (30.3387, 81.8778) radius 5 clockwise from (26.5387, 78.6282) to (25.3387, 81.8778)
  arc A7 centre (20.3387, 97.7538) radius 5 clockwise from (20.3387, 102.7538) to (25.3387, 97.7538)
  arc A8 centre (-105.8913, 97.7538) radius 5 clockwise from (-110.8913, 97.7538) to (-105.8913, 102.7538)
  arc A9 centre (-115.8913, 81.8778) radius 5 clockwise from (-110.8913, 81.8778) to (-112.0913, 78.6282)
  arc A10 centre (-106.3913, 73.7538) radius 7.5 clockwise from (-113.8913, 73.7538) to (-112.0913, 78.6282)
  arc A11 centre (-106.3913, -216.7462) radius 7.5 clockwise from (-112.0913, -221.6206) to (-113.8913, -216.7462)
  arc A12 centre (-115.8913, -224.8703) radius 5 clockwise from (-112.0913, -221.6206) to (-110.8913, -224.8703)
  circle C1 centre (-14.3395, 1.258) radius 1.1
  circle C2 centre (-41.9342, -214.0862) radius 3.175
  circle C3 centre (-49.7352, -209.6412) radius 3.175
  circle C4 centre (-57.4342, -214.0862) radius 3.175
  circle C5 centre (-42.0363, -205.1962) radius 3.175
  circle C6 centre (-34.3047, -209.6409) radius 3.175
  circle C7 centre (-57.4342, -205.1962) radius 3.175
  circle C8 centre (-42.0363, -196.3062) radius 3.175
  circle C9 centre (-57.4342, -196.3062) radius 3.175
  circle C10 centre (-72.8037, -205.1959) radius 3.175
  circle C11 centre (-65.1332, -182.9712) radius 3.175
  circle C12 centre (-49.7068, -182.9709) radius 3.175
  circle C13 centre (-65.1332, -191.8612) radius 3.175
  circle C14 centre (-80.5027, -200.7509) radius 3.175
  circle C15 centre (-88.2342, -187.4162) radius 3.175
  circle C16 centre (-72.8037, -178.5259) radius 3.175
  circle C17 centre (-57.4058, -169.6359) radius 3.175
  circle C18 centre (-72.8037, -169.6359) radius 3.175
  circle C19 centre (-95.9332, -182.9712) radius 3.175
  circle C20 centre (-95.9332, -165.1912) radius 3.175
  circle C21 centre (-95.9332, -174.0812) radius 3.175
  circle C22 centre (-72.8037, -160.7459) radius 3.175
  circle C23 centre (-88.2342, -160.7462) radius 3.175
  circle C24 centre (-80.5027, -156.3009) radius 3.175
  circle C25 centre (-72.8037, -142.9659) radius 3.175
  circle C26 centre (-88.2342, -151.8562) radius 3.175
  circle C27 centre (-95.9332, -138.5212) radius 3.175
  circle C28 centre (-80.5027, -138.5209) radius 3.175
  circle C29 centre (-72.8037, -134.0759) radius 3.175
  circle C30 centre (-88.2342, -134.0762) radius 3.175
  circle C31 centre (-88.2342, -142.9662) radius 3.175
  circle C32 centre (-95.9332, -147.4112) radius 3.175
  circle C33 centre (-80.5027, -147.4109) radius 3.175
  circle C34 centre (-72.8037, -151.8559) radius 3.175
  circle C35 centre (-95.9332, -156.3012) radius 3.175
  circle C36 centre (-80.5027, -165.1909) radius 3.175
  circle C37 centre (-65.1047, -156.3009) radius 3.175
  circle C38 centre (-88.2342, -169.6362) radius 3.175
  circle C39 centre (-88.2342, -178.5262) radius 3.175
  circle C40 centre (-80.5027, -174.0809) radius 3.175
  circle C41 centre (-65.1047, -165.1909) radius 3.175
  circle C42 centre (-65.1047, -174.0809) radius 3.175
  circle C43 centre (-80.5027, -182.9709) radius 3.175
  circle C44 centre (-80.5027, -191.8609) radius 3.175
  circle C45 centre (-72.8037, -196.3059) radius 3.175
  circle C46 centre (-57.4342, -187.4162) radius 3.175
  circle C47 centre (-57.4058, -178.5259) radius 3.175
  circle C48 centre (-72.8037, -187.4159) radius 3.175
  circle C49 centre (-65.1332, -200.7512) radius 3.175
  circle C50 centre (-49.7352, -191.8612) radius 3.175
  circle C51 centre (-49.7027, -200.7509) radius 3.175
  circle C52 centre (-65.1332, -209.6412) radius 3.175
  circle C53 centre (-88.2342, -196.3062) radius 3.175
  circle C54 centre (-95.9332, -191.8612) radius 3.175
  circle C55 centre (-72.8037, -214.0859) radius 3.175
  circle C56 centre (-80.5027, -209.6409) radius 3.175
  circle C57 centre (-88.2342, -205.1962) radius 3.175
  circle C58 centre (-95.9332, -200.7512) radius 3.175
  circle C59 centre (-95.9332, -209.6412) radius 3.175
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  horizontal L42
  vertical L43
  horizontal L44
  vertical L45
  horizontal L46
  vertical L47
  horizontal L48
  vertical L49
extrude "Extrude54" cut sketch "Sketch193" profile of L42 L43 L44 L45 L46 L47 L48 L49 against normal blind 10
move "Move7"
move "Move8"
delete_face "DeleteFace37"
